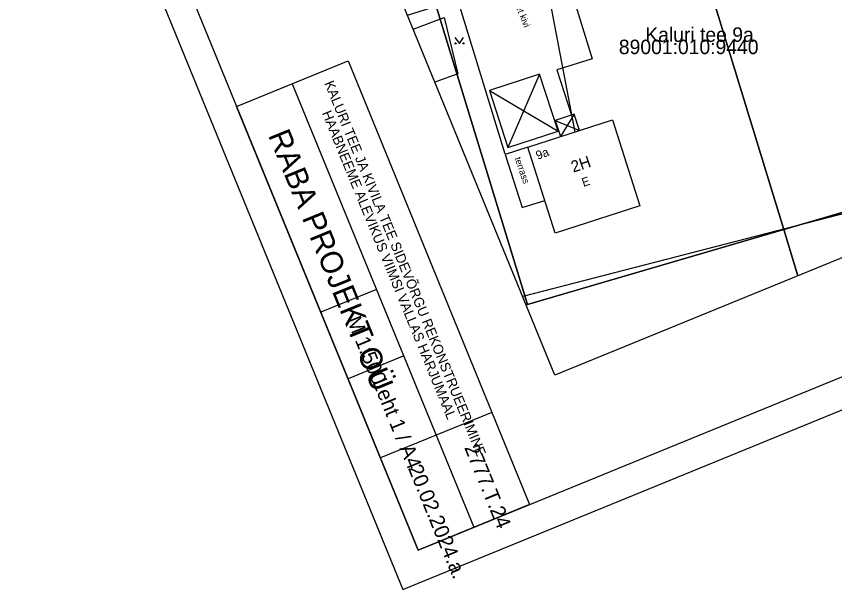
# Model space of a CAD drawing. Extents: x -52238384 to 549205, y 6582846 to 57187752.
# Drawn here: x 546435.6 to 546520.5, y 6597120.1 to 6597179.7 of the extents above; entities that cross this region are included whole.
import ezdxf

# ---------------------------------------------------------------- set-up
doc = ezdxf.new("R2010")
doc.units = 0
for name, color, linetype in [('kaluri tee mõõdistus$0$HALJASTUS', 7, 'Continuous'), ('kaluri tee mõõdistus$0$HOONE', 7, 'Continuous'), ('kaluri tee mõõdistus$0$HOONEDET', 7, 'Continuous'), ('kaluri tee mõõdistus$0$SITRASS', 7, 'Continuous'), ('kaluri tee mõõdistus$0$TEE', 7, 'Continuous'), ('L_AADRESS', 7, 'Continuous'), ('Level 52', 7, 'Continuous'), ('Level 63', 7, 'Continuous'), ('PIIR', 7, 'Continuous'), ('TUNNUS', 7, 'Continuous')]:
    doc.layers.add(name, color=color, linetype=linetype)

# ---------------------------------------------------------------- blocks, each defined once
blk = doc.blocks.new('kaluri tee mõõdistus$0$MURU')
at = {"layer": 'kaluri tee mõõdistus$0$HALJASTUS'}
for p, q in [((-93, 121), (0, 0)), ((0, 0), (89, 121))]:
    blk.add_line(p, q, dxfattribs=at)
for centre in [(-80, 0), (86, 0)]:
    blk.add_circle(centre, 11, dxfattribs=at)

msp = doc.modelspace()

# ---------------------------------------------------------------- linework, layer by layer
at = {"layer": 'kaluri tee mõõdistus$0$HOONE'}
for points in [[(546476.776, 6597178.318), (546479.994, 6597179.534)], [(546479.994, 6597179.534), (546481.409, 6597173.706), (546479.019, 6597172.837)], [(546489.901, 6597173.661), (546484.69, 6597171.974), (546486.581, 6597166.042), (546491.816, 6597167.734), (546489.901, 6597173.661)], [(546494.026, 6597167.807), (546493.482, 6597169.49), (546491.523, 6597168.857), (546492.067, 6597167.174)], [(546488.663, 6597166.074), (546497.453, 6597168.914), (546500.296, 6597159.992), (546491.506, 6597157.152), (546488.663, 6597166.074)], [(546488.663, 6597166.074), (546486.31, 6597165.314), (546488.068, 6597159.798), (546490.424, 6597160.548)]]:
    msp.add_lwpolyline(points, dxfattribs=at)
at = {"layer": 'kaluri tee mõõdistus$0$HOONEDET'}
for p, q in [((546489.901, 6597173.661), (546486.581, 6597166.042)), ((546484.69, 6597171.974), (546491.816, 6597167.734)), ((546493.482, 6597169.49), (546492.067, 6597167.174)), ((546491.523, 6597168.857), (546494.026, 6597167.807))]:
    msp.add_line(p, q, dxfattribs=at)
at = {"layer": 'kaluri tee mõõdistus$0$SITRASS'}
msp.add_line((546489.56, 6597188.78), (546493.538, 6597167.649), dxfattribs=at)
at = {"layer": 'kaluri tee mõõdistus$0$TEE'}
for points in [[(546583.191, 6597186.42), (546549.279, 6597166.35), (546488.139, 6597150.551)], [(546488.099, 6597184.127), (546488.208, 6597183.721), (546492.368, 6597184.96), (546495.351, 6597175.243), (546491.692, 6597174.115), (546493.192, 6597169.417)], [(546481.24, 6597181.882), (546486.29, 6597165.376)]]:
    msp.add_lwpolyline(points, dxfattribs=at)
at = {"layer": 'Level 52'}
for p, q in [((546464.219, 6597172.666), (546483.072, 6597126.595)), ((546472.964, 6597151.297), (546467.18, 6597148.93)), ((546475.791, 6597144.386), (546470.008, 6597142.02)), ((546484.941, 6597138.527), (546473.374, 6597133.794))]:
    msp.add_line(p, q, dxfattribs=at)
for points in [[(546610.665, 6597175.343), (546570.526, 6597273.43), (546435.57, 6597218.204), (546475.709, 6597120.117)], [(546439.31, 6597217.036), (546477.288, 6597124.229), (546607.423, 6597177.482), (546569.445, 6597270.289)], [(546556.701, 6597251.154), (546585.474, 6597180.84), (546491.483, 6597142.378), (546462.71, 6597212.692)], [(546470.003, 6597175.033), (546488.855, 6597128.962), (546477.288, 6597124.229), (546458.435, 6597170.299)]]:
    msp.add_lwpolyline(points, close=True, dxfattribs=at)
at = {"layer": 'PIIR'}
for points in [[(546529.93, 6597196.26), (546547.7, 6597167.01), (546544.44, 6597166.05), (546515.25, 6597157.51), (546505.65, 6597188.82), (546515.76, 6597191.92)], [(546479.16, 6597180.71), (546505.65, 6597188.82), (546515.25, 6597157.51), (546488.65, 6597149.72)]]:
    msp.add_lwpolyline(points, close=True, dxfattribs=at)
for points in [[(546476.173, 6597179.793), (546479.16, 6597180.71), (546488.65, 6597149.72), (546488.497, 6597149.675)], [(546516.697, 6597152.696), (546515.25, 6597157.51), (546544.44, 6597166.05), (546545.366, 6597164.427)], [(546488.497, 6597149.675), (546488.65, 6597149.72), (546515.25, 6597157.51), (546516.697, 6597152.696)]]:
    msp.add_lwpolyline(points, dxfattribs=at)

# ---------------------------------------------------------------- block references
at = {"layer": 'kaluri tee mõõdistus$0$HALJASTUS', "xscale": 0.005000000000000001, "yscale": 0.005000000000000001, "rotation": -4.073594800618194e-10}
msp.add_blockref('kaluri tee mõõdistus$0$MURU', (546481.565, 6597176.861), dxfattribs=at)

# ---------------------------------------------------------------- texts
at = {"layer": 'kaluri tee mõõdistus$0$HOONE'}
for s, height, rotation, p in [('9a', 0.9, 20.95052, (546489.711, 6597164.752)), ('2H', 1.2, 18.67265, (546493.386, 6597163.416)), ('E', 0.9, 18.70905, (546494.453, 6597161.944))]:
    msp.add_text(s, height=height, rotation=rotation, dxfattribs=at).set_placement(p)
at = {"layer": 'kaluri tee mõõdistus$0$HOONEDET'}
msp.add_text('terrass', height=0.7, rotation=289.26863, dxfattribs=at).set_placement((546487.283, 6597164.912))
at = {"layer": 'kaluri tee mõõdistus$0$TEE'}
msp.add_text('bet kivi', height=0.7, rotation=291.84278, dxfattribs=at).set_placement((546487.219, 6597181.143))
at = {"layer": 'L_AADRESS'}
msp.add_text('Kaluri tee 9a', height=1.5, rotation=360, dxfattribs=at).set_placement((546500.867, 6597177.019))
at = {"layer": 'Level 52'}
for s, height, p in [('RABA PROJEKT OÜ', 2.30836, (546461.679, 6597167.329)), ('M 1:500', 1.5389, (546469.835, 6597148.146)), ('Leht 1 / A4', 1.53891, (546472.518, 6597141.693)), ('2777.T.24', 1.5389, (546482.055, 6597134.878)), ('20.02.2024.a.', 1.53891, (546476.208, 6597132.746))]:
    msp.add_text(s, height=height, rotation=292.25515, dxfattribs=at).set_placement(p)
at = {"layer": 'Level 63'}
for s, p in [('KALURI TEE JA KIVILA TEE SIDEVÕRGU REKONSTRUEERIMINE', (546467.523, 6597172.721)), ('HAABNEEME ALEVIKUS VIIMSI VALLAS HARJUMAAL', (546467.276, 6597169.628))]:
    msp.add_text(s, height=1.02722, rotation=292.24769, dxfattribs=at).set_placement(p)
at = {"layer": 'TUNNUS'}
msp.add_text('89001:010:9440', height=1.5, rotation=360, dxfattribs=at).set_placement((546498.124, 6597175.741))

doc.saveas('drawing.dxf')
